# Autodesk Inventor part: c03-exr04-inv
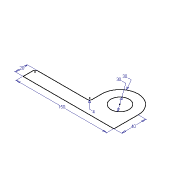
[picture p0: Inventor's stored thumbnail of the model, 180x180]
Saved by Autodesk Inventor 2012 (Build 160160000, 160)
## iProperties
Shininess: 64.0
Length Units: 11269
Angle Units: 11279
Time Units: 11290
Mass Units: 11283
Length Display Precision: 3
Angle Display Precision: 2
Compacted: True
Created: 2002-02
Part Number: c03-exr04-inv
Document SubType Name: Modeling
Density: 1 g/cm^3
Material: Default
Density: 0.0
Volumn: 0.0
Area: 0.0
PropertySet Name: Model Information
Control State: 0
Master: False
Checked Out: False
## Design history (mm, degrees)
sketch "Sketch1"
  geometry: L1 (-66.957, -29.14)-(83.043, -29.14); L2 (83.043, -29.14)-(83.043, 10.86); L3 (23.043, 10.86)-(23.043, -5.14); L4 (19.043, -9.14)-(-62.957, -9.14); L5 (-66.957, -13.14)-(-66.957, -29.14); C1 r 15 at (53.043, 10.86); A1 r 30 centre (53.043, 10.86) between (83.043, 10.86) and (23.043, 10.86); A2 r 4 centre (19.043, -5.14) between (19.043, -9.14) and (23.043, -5.14); A3 r 4 centre (-62.957, -13.14) between (-62.957, -9.14) and (-66.957, -13.14)
  constraints: 10 end point, 6 point on circle, 6 tangent, 4 centre point, 3 parallel, 1 coincident, 1 equal radius, 1 horizontal, 1 perpendicular
  dimensions: "d0" = 150 distance of L1.start L1.end; "d1" = 40 distance of L1.end L2.end; "d2" = 30 radius of A1; "d4" = 4 radius of A2; "d5" = 20 distance between parallel lines of L1 L4; "d6" = 30 diameter of C1
